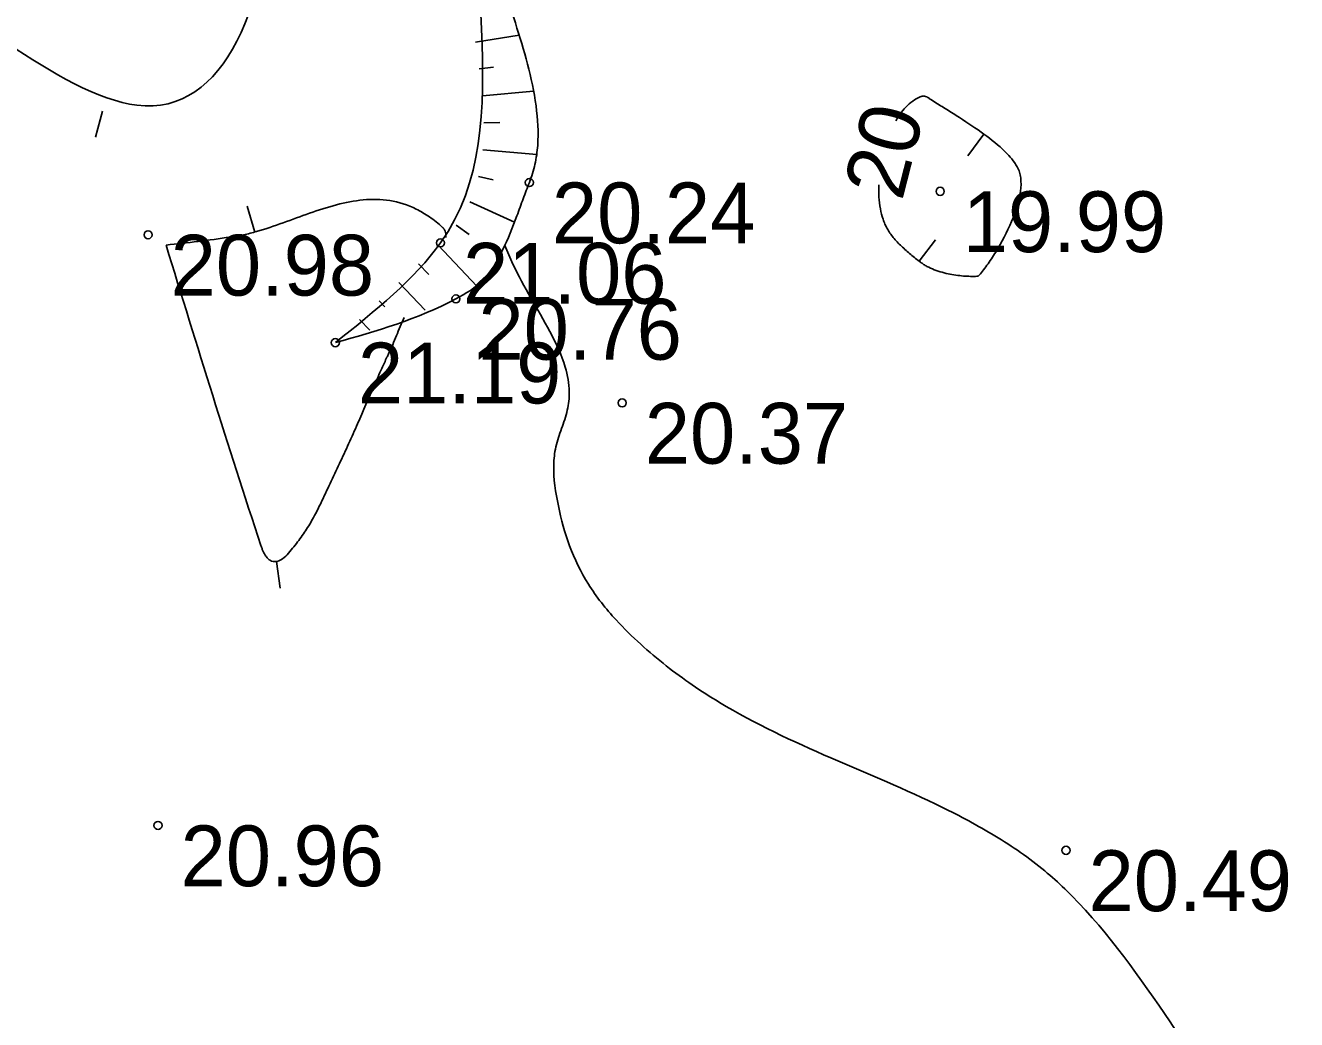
# Model space of a CAD drawing. Extents: x 521824 to 524158, y 294774 to 296228.
# Drawn here: x 522012.82 to 522036.35, y 295824.83 to 295843.22 of the extents above; entities that cross this region are included whole.
import ezdxf

# ---------------------------------------------------------------- set-up
doc = ezdxf.new("R2010")
doc.units = 0
for name, color, linetype in [('RELJ_AATZ_####_TKST_#', 7, 'Continuous'), ('RELJ_ELEM_####_####_#', 7, 'Continuous'), ('RELJ_HORZ_####_TKST_#', 7, 'Continuous'), ('RELJ_HORZ_PAMT_####_#', 7, 'Continuous'), ('RELJ_HORZ_RESN_####_#', 7, 'Continuous'), ('RELJ_NOGA_####_####_#', 7, 'Continuous'), ('RELJ_NOGL_####_####_#', 7, 'Continuous')]:
    doc.layers.add(name, color=color, linetype=linetype)

msp = doc.modelspace()

# ---------------------------------------------------------------- linework, layer by layer
at = {"layer": 'RELJ_ELEM_####_####_#'}
for centre in [(522022.146, 295840.316), (522029.749, 295840.153), (522015.09, 295839.349), (522020.50100000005, 295839.199), (522020.786, 295838.163), (522018.55600000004, 295837.353), (522023.864, 295836.238), (522015.27400000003, 295828.418), (522032.07800000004, 295827.957)]:
    msp.add_circle(centre, 0.075, dxfattribs=at)
at = {"layer": 'RELJ_HORZ_PAMT_####_#'}
for p, q in [((522014.11740016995, 295841.15612391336), (522014.2464446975, 295841.63918447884)), ((522016.92311437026, 295839.87930289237), (522017.0646110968, 295839.3997419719)), ((522017.53584021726, 295832.80696418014), (522017.4634709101, 295833.3016991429))]:
    msp.add_line(p, q, dxfattribs=at)
for points in [[(522039.85105248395, 295883.2337945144), (522039.8032764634, 295883.09412122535), (522039.6036826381, 295882.72640522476), (522038.55198012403, 295881.74642886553), (522037.24460411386, 295881.26963240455), (522035.87605298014, 295881.1684432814), (522029.62574498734, 295881.1250179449), (522028.3640343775, 295881.1156959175), (522027.73340432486, 295881.0942865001), (522027.10293182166, 295881.045318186), (522026.9348494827, 295880.8792425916), (522026.04491836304, 295879.0357926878), (522025.56662292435, 295877.8705193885), (522025.13096822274, 295876.6906595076), (522024.6784930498, 295875.509178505), (522024.1497361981, 295874.33904184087), (522023.1278022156, 295873.1202038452), (522022.45149386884, 295872.68855173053), (522021.718485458, 295872.3952945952), (522015.97858872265, 295871.9813647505), (522010.28566270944, 295873.3184813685), (522007.25729819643, 295874.6412358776), (522004.9722147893, 295876.36413812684), (522001.44201012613, 295878.6938834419), (521999.66114804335, 295879.6846711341), (521998.77242067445, 295880.0998103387), (521997.88697903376, 295880.44745277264), (521997.4959793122, 295880.4513396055), (521997.1092043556, 295880.23749301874), (521996.7340608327, 295879.87949182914), (521996.3779554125, 295879.45091485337), (521996.27616427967, 295879.0013078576), (521996.400274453, 295878.5538101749), (521996.8112803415, 295876.93516905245), (521997.1304580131, 295876.16157373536), (521997.6255973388, 295875.4531083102), (521999.24205179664, 295874.08337536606), (522001.01972147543, 295873.0615806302), (522002.8160713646, 295872.1323525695), (522003.67670919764, 295871.6226474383), (522004.48856645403, 295871.0403196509), (522005.06238406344, 295870.5370640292), (522005.6183839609, 295869.99889289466), (522006.1747109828, 295869.460970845), (522006.7495099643, 295868.9584624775), (522007.0070353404, 295868.85625760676), (522007.225831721, 295868.358889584), (522007.0915773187, 295860.8566492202), (522006.9208173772, 295855.8522134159), (522006.6846767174, 295848.9635027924), (522006.74219449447, 295846.87223905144), (522006.7634501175, 295846.5472356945), (522006.5524396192, 295845.2855568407), (522006.09686690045, 295844.1004188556), (522005.7434075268, 295843.61117697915), (522005.5208611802, 295843.426169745), (522005.262285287, 295843.2937742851), (522003.6445183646, 295843.19012527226), (522001.9994780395, 295843.7543531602), (522000.3301660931, 295844.5192909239), (521999.48734631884, 295844.83103631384), (521998.6395843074, 295845.01777153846), (521997.75563936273, 295845.08268233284), (521997.2109762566, 295844.8845836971), (521996.8583636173, 295844.45723979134), (521996.62520253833, 295844.00645984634), (521996.3326074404, 295843.04478261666), (521995.08116115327, 295838.05999353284), (521994.3171783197, 295833.02519397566), (521994.3254759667, 295831.74490356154), (521994.5353443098, 295830.4213550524), (521995.2569333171, 295829.63050990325), (521996.84168272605, 295828.8094427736), (521998.53761528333, 295828.25008483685), (522000.20764485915, 295827.67176067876), (522001.71468532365, 295826.7937948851), (522007.3320723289, 295820.83228229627), (522008.9147475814, 295818.1640307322), (522008.6042579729, 295814.9642406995), (522007.87451118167, 295814.0011593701), (522007.09756741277, 295813.11117719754), (522006.2702075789, 295812.2782132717), (522005.389212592, 295811.4861866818), (522001.2557309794, 295808.1438601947), (522000.1303116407, 295807.3706090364), (521998.96385563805, 295806.65336808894), (521997.7930222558, 295805.9482845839), (521996.6544707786, 295805.21150575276), (521996.38234203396, 295804.9480935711), (521996.15736309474, 295804.6301419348), (521995.9240970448, 295804.3146908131), (521995.6271069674, 295804.05878017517), (521994.03230866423, 295803.93852662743), (521993.54953046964, 295804.1273633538), (521993.0711955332, 295804.3438837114), (521992.5902990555, 295804.55881235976), (521992.0998362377, 295804.74287395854), (521988.9608554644, 295805.61124198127), (521982.64622882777, 295805.9659620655)], [(522008.128, 295848.335), (522008.2689477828, 295847.83384447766), (522012.49599618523, 295842.88903796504), (522014.8830624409, 295841.7470574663), (522016.1223240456, 295853.9072460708), (522015.27368849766, 295855.37330890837), (522014.846287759, 295856.25687423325), (522014.1497888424, 295858.06888958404), (522011.2980547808, 295858.5380575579), (522008.60002352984, 295854.29462215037), (522008.199583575, 295850.21910016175), (522008.128, 295848.335)], [(522020.59982497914, 295839.29797052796), (522020.60242294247, 295839.3453689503), (522020.59656443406, 295839.3927218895), (522020.5775423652, 295839.439193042), (522020.5616240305, 295839.46183660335), (522020.55180561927, 295839.47296464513), (522020.54639942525, 295839.4784745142), (522020.54064964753, 295839.4839461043), (522020.4189498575, 295839.58891256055), (522020.2970543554, 295839.68044139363), (522020.0527249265, 295839.82570962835), (522019.56225334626, 295839.98275244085), (522018.5767871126, 295839.9041759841), (522017.5904859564, 295839.571216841), (522017.0989707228, 295839.4102812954), (522016.85396291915, 295839.34886359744), (522016.6095848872, 295839.3068751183), (522015.422, 295839.158)], [(522015.422, 295839.158), (522017.17756001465, 295833.60029999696), (522017.19825370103, 295833.54041225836), (522017.22020120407, 295833.4876165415), (522017.2677147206, 295833.4026369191), (522017.31750571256, 295833.3474633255), (522017.34641107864, 295833.3261461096), (522017.37621522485, 295833.31047514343), (522017.51191183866, 295833.3153977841), (522017.6391055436, 295833.40014325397), (522017.7401793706, 295833.51719841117), (522017.8343231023, 295833.63474375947), (522018.00401694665, 295833.8732729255), (522018.1525804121, 295834.1196665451), (522018.2844068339, 295834.3778604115), (522018.45810594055, 295834.74571885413), (522018.6311366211, 295835.113454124), (522018.80147433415, 295835.48224132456), (522018.9670945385, 295835.8532555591), (522019.27671787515, 295836.5650211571), (522019.41559484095, 295836.8772227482), (522019.510905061, 295837.0835450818), (522019.5407993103, 295837.14613278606), (522019.6166244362, 295837.31422385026), (522019.6865798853, 295837.4830965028), (522019.75632240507, 295837.6510294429), (522019.8315087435, 295837.8163013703), (522019.83150875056, 295837.8163013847)], [(522061.741970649, 295824.8831938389), (522061.5520604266, 295824.78178038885), (522061.38605545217, 295824.74946375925), (522061.1718963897, 295824.81851527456), (522060.5310572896, 295824.96082909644), (522060.20688746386, 295824.9847778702), (522059.8960030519, 295824.9372926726), (522058.9889245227, 295824.33355464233), (522058.2956968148, 295823.37754064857), (522057.63291155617, 295822.3510845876), (522056.8171603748, 295821.5360203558), (522055.7262286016, 295820.8165031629), (522054.6152811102, 295820.105665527), (522053.4647294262, 295819.4691455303), (522052.25498507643, 295818.97258125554), (522047.30389492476, 295817.4178311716), (522043.97857530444, 295816.3212293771), (522043.21024391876, 295816.09499166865), (522042.41581105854, 295815.93624896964), (522041.62055172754, 295815.8963398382), (522041.2305105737, 295815.93699115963), (522040.8497409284, 295816.02660283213), (522039.80729485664, 295816.6465061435), (522038.94238886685, 295817.56506427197), (522037.1347181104, 295819.9756890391), (522035.5230144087, 295822.47335156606), (522033.8989985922, 295824.93675610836), (522032.05439149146, 295827.2446069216), (522031.68451634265, 295827.5776987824), (522030.7614068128, 295828.22486618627), (522029.7812756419, 295828.75707069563), (522027.7247754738, 295829.6683527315), (522025.66467003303, 295830.6950682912), (522024.680032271, 295831.37156470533), (522024.2072513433, 295831.7715715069), (522023.7506135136, 295832.2207407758), (522023.2382105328, 295832.8863053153), (522022.88963891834, 295833.5950921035), (522022.68313822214, 295834.33264938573), (522022.59694799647, 295835.08452540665), (522022.6368390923, 295835.42385731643), (522022.7423851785, 295835.763263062), (522022.8474568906, 295836.10303231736), (522022.88592486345, 295836.44345475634), (522022.81064079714, 295836.89677727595), (522022.5244666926, 295837.5583554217), (522022.1756120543, 295838.18152233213), (522021.8431745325, 295838.80350512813), (522021.6943038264, 295839.1549252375)], [(521998.95200000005, 295776.033), (521994.45180056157, 295777.14810434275), (521993.7404927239, 295777.11440045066), (521993.21262549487, 295776.6759437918), (521992.4953181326, 295775.0009956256), (521991.87608901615, 295772.9557067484), (521991.47081959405, 295772.05432420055), (521990.9311486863, 295771.37252406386), (521990.1398086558, 295770.77466894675), (521989.7352167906, 295770.4754847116), (521989.3530874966, 295770.1518434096), (521988.9164089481, 295769.6848393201), (521987.5681602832, 295767.21577675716), (521984.7771736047, 295762.2741632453), (521984.65230933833, 295760.3982510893), (521984.50330046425, 295759.4917473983), (521984.3585855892, 295758.58690105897), (521984.3353209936, 295757.6981352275), (521984.48002007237, 295757.3757561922), (521984.7063801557, 295757.0946927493), (521985.3082013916, 295756.7669212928), (521985.9519889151, 295756.72591082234), (521986.6068210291, 295756.80455120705), (521987.25649307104, 295756.9672667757), (521987.88480037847, 295757.17848185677), (521990.0305543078, 295757.99091302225), (521991.5170457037, 295758.46493880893), (521993.0217429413, 295758.88756110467), (521994.5233797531, 295759.3350657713), (521995.26640479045, 295759.59198832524), (521996.00068987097, 295759.88373867), (521997.05489538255, 295760.78736771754), (521997.55051264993, 295761.41710623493), (522000.3434912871, 295763.67917371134), (522000.94593386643, 295764.02787890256), (522003.2754265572, 295764.87055882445), (522004.55090309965, 295765.2234577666), (522005.83615178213, 295765.5370160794), (522007.12200246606, 295765.8503377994), (522008.3992850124, 295766.20252696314), (522009.65331824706, 295766.72165083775), (522011.3602020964, 295767.63989140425), (522012.969612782, 295768.6931675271), (522014.47229228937, 295769.89709722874), (522015.1807147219, 295770.5604378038), (522015.8589826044, 295771.26729853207), (522016.2597702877, 295771.87912286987), (522016.53298413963, 295772.5634778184), (522016.7931695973, 295773.25320618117), (522017.15487209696, 295773.88115076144), (522018.18949794, 295774.9696944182), (522018.4476509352, 295775.1878853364), (522019.2876896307, 295775.72172549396), (522020.4949333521, 295776.3014989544), (522021.6983824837, 295776.96563647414), (522022.26341950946, 295777.40953602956), (522022.5305948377, 295777.67347750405), (522022.78519040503, 295777.97075972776), (522023.2010017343, 295778.803778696), (522023.2392845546, 295779.6483704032), (522023.0122548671, 295780.4841053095), (522022.6658204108, 295781.3170062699), (522022.31136664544, 295782.1521974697), (522022.0602790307, 295782.9948030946), (522021.8800262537, 295784.34168614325), (522021.8683239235, 295785.71352772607), (522021.9466292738, 295786.68962457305), (522022.13179647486, 295787.705289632), (522022.5219133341, 295788.5528666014), (522023.2150676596, 295789.0246991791), (522026.40113487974, 295789.6656407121), (522029.5910643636, 295790.20565416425), (522031.1198177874, 295790.45930455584), (522031.8833809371, 295790.592832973), (522032.2641433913, 295790.66813436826), (522032.6439156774, 295790.75174108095), (522034.34009166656, 295791.613047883), (522035.89075127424, 295792.7974618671), (522039.32693267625, 295795.1720253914), (522041.99268416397, 295796.8267501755), (522044.5121990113, 295798.984097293), (522044.9056368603, 295799.5506320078), (522045.47650309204, 295800.55810906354), (522045.99759169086, 295801.59089799), (522046.5214402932, 295802.62769177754), (522047.1005865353, 295803.6471834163), (522049.4664640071, 295806.9793396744), (522050.94743011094, 295808.28937408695), (522051.7905227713, 295808.76012787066), (522052.71272765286, 295809.0717527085), (522053.5514493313, 295809.2031588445), (522054.3939016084, 295809.26977886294), (522056.18416763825, 295809.39970149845), (522057.9448874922, 295809.5837619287), (522059.7026316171, 295809.81589361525), (522061.4611590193, 295810.04426197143), (522063.22422870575, 295810.21703241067), (522064.1655150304, 295810.1470657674), (522066.93228605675, 295809.9065813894), (522068.31554527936, 295810.0098516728), (522069.00682868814, 295810.20883838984), (522069.35234451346, 295810.3566038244), (522069.69776143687, 295810.5409065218), (522070.4955259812, 295811.1688285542), (522071.0813307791, 295811.9043088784), (522071.5717992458, 295812.6925002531), (522071.81772717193, 295813.0892228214), (522072.08355479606, 295813.4785554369), (522072.40604720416, 295814.0003097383), (522072.7676993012, 295814.4937868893), (522073.1254027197, 295814.75396744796), (522073.5336405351, 295814.93279178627), (522073.95939591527, 295815.08768923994), (522074.369652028, 295815.27608914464), (522075.0954593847, 295815.66872097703), (522075.81475551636, 295816.0696827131), (522076.4764910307, 295816.5373865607), (522076.76982062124, 295816.81452059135), (522077.029616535, 295817.1302447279), (522077.3485357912, 295818.0711955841), (522077.2140011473, 295819.12112619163), (522076.82493924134, 295820.19231449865), (522076.38027671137, 295821.19703845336), (522075.40752943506, 295823.31140125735), (522075.07482163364, 295824.3220648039), (522074.8158376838, 295825.3634059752), (522074.5088306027, 295826.3931939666), (522074.2992724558, 295826.89055839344), (522074.0320534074, 295827.3691979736), (522073.5498181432, 295827.83794916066), (522072.9888231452, 295828.2044779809), (522072.5737168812, 295828.40410874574), (522072.0614797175, 295828.59496277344), (522071.7062148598, 295828.76573362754), (522071.6668542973, 295828.8400546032), (522071.7620255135, 295828.9051148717), (522072.44228643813, 295829.09140054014), (522073.12896814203, 295829.19107671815), (522075.3108758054, 295828.6989870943), (522076.9489012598, 295827.7002041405), (522079.1396826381, 295828.4298136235), (522079.996228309, 295829.49230765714), (522079.62960017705, 295830.75335929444), (522079.41251941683, 295831.52017392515)]]:
    msp.add_spline(points, degree=3, dxfattribs=at)
at = {"layer": 'RELJ_HORZ_RESN_####_#'}
for p, q in [((522030.2618123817, 295840.80913771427), (522030.55606014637, 295841.21338794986)), ((522029.6653020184, 295839.25665146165), (522029.3593626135, 295838.8611756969))]:
    msp.add_line(p, q, dxfattribs=at)
for points in [[(522030.4550113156, 295838.58175111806), (522030.5329291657, 295838.6768835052), (522030.61357157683, 295838.78453507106), (522030.77694118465, 295839.0302383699), (522031.0693972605, 295839.59314406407), (522031.234957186, 295840.1559503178), (522031.23970660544, 295840.40152931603), (522031.2172458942, 295840.50910008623), (522031.1991407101, 295840.558297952), (522031.1882861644, 295840.58165215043), (522031.17619860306, 295840.60413924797), (522031.1228061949, 295840.68678699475), (522030.90318291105, 295840.9313983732), (522030.5068557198, 295841.2488145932), (522030.0475793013, 295841.55474572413), (522029.8131983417, 295841.7028911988), (522029.5857159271, 295841.8475495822), (522029.5437247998, 295841.87505110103), (522029.4996840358, 295841.90052567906), (522029.4560327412, 295841.91610713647), (522029.43511536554, 295841.9177297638), (522029.4250171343, 295841.9165688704), (522029.41521002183, 295841.9139292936), (522029.2741144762, 295841.84425091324), (522029.1452147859, 295841.74226743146), (522029.0290034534, 295841.6122194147), (522028.9758098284, 295841.5379963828), (522028.9259729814, 295841.45834742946)], [(522028.61227817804, 295840.2763621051), (522028.6117358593, 295840.16062782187), (522028.6166437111, 295840.047533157), (522028.64317076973, 295839.8323696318), (522028.6925810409, 295839.6370854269), (522028.7260929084, 295839.54883991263), (522028.74508999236, 295839.50740612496), (522028.76559621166, 295839.46789443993), (522028.8817430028, 295839.2996473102), (522029.03233743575, 295839.1383042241), (522029.20417272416, 295838.98532258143), (522029.2939285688, 295838.91242273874), (522029.38404208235, 295838.84215978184), (522029.4425571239, 295838.8011400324), (522029.5052402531, 295838.7642572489), (522029.6405004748, 295838.70218451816), (522029.93232467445, 295838.6197839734), (522030.21774988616, 295838.5834691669), (522030.34501137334, 295838.5790036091), (522030.40249532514, 295838.57956548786), (522030.4550113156, 295838.58175111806)]]:
    msp.add_spline(points, degree=3, dxfattribs=at)
at = {"layer": 'RELJ_NOGA_####_####_#'}
for p, q in [((522021.1463987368, 295842.91255650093), (522021.95668490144, 295843.04196290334)), ((522021.2201645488, 295842.41804363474), (522021.4846160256, 295842.4533990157)), ((522021.2761571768, 295841.92123562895), (522022.2241062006, 295842.00710660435)), ((522021.3028946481, 295841.42206164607), (522021.6019640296, 295841.42745515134)), ((522021.2852698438, 295840.92260808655), (522022.28235274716, 295840.8354025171)), ((522021.2049488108, 295840.42956618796), (522021.4747006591, 295840.3634775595)), ((522021.0434406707, 295839.95716491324), (522021.87192941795, 295839.581280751)), ((522020.79116274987, 295839.52655083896), (522021.03025439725, 295839.35172327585)), ((522020.4561429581, 295839.15642617), (522021.17531129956, 295838.3986892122)), ((522020.0934803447, 295838.81222299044), (522020.2842050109, 295838.61126986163)), ((522019.7308177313, 295838.46801981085), (522020.2166054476, 295837.9561795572)), ((522019.3681551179, 295838.1238166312), (522019.46890308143, 295838.0176656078)), ((522019.0054925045, 295837.77961345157), (522019.19135787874, 295837.58378021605)), ((522018.6428298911, 295837.435410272), (522018.65360115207, 295837.424061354))]:
    msp.add_line(p, q, dxfattribs=at)
msp.add_spline([(522018.55600000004, 295837.353), (522020.50100000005, 295839.199), (522021.477, 295848.18), (522028.416, 295855.248), (522030.764, 295852.519), (522039.31600000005, 295853.821), (522047.42000000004, 295849.505), (522051.81100000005, 295848.394), (522054.114, 295850.7040000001), (522056.37600000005, 295853.1390000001), (522063.96900000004, 295845.04000000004)], degree=3, dxfattribs=at)
at = {"layer": 'RELJ_NOGL_####_####_#'}
msp.add_spline([(522018.55600000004, 295837.353), (522020.786, 295838.163), (522021.29201399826, 295838.51486265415), (522021.65031370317, 295839.06336455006), (522021.9164565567, 295839.69993417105), (522022.0323308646, 295840.01731577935), (522022.146, 295840.316), (522022.2497575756, 295840.65282321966), (522022.3000511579, 295841.0028959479), (522022.26939318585, 295841.73475341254), (522021.8871245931, 295843.26906074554), (522021.4655437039, 295844.7903377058), (522021.38574536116, 295845.50590720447), (522021.471, 295846.17000000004), (522021.55386910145, 295846.3219582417), (522021.6882953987, 295846.41378726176), (522022.0827355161, 295846.4508374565), (522023.1703773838, 295846.17496520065), (522024.26858055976, 295845.88286034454), (522024.676222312, 295845.89961978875), (522024.81922967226, 295845.9782598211), (522024.912, 295846.115), (522024.8306145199, 295846.7553688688), (522024.3916502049, 295847.48063000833), (522023.97001916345, 295848.2214333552), (522023.9406335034, 295848.90842884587)], degree=3, dxfattribs=at)

# ---------------------------------------------------------------- texts
at = {"layer": 'RELJ_AATZ_####_TKST_#'}
for s, p in [(' 20.24', (522022.146, 295839.191)), (' 19.99', (522029.749, 295839.028)), (' 20.98', (522015.09, 295838.224)), (' 21.06', (522020.50100000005, 295838.074)), (' 20.76', (522020.786, 295837.038)), (' 21.19', (522018.55600000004, 295836.228)), (' 20.37', (522023.864, 295835.113)), (' 20.96', (522015.27400000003, 295827.293)), (' 20.49', (522032.07800000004, 295826.832))]:
    msp.add_text(s, height=1.125, dxfattribs=at).set_placement(p)
at = {"layer": 'RELJ_HORZ_####_TKST_#'}
msp.add_text('20', height=1.1249999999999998, rotation=75.66136157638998, dxfattribs=at).set_placement((522029.04171979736, 295839.95831966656))

doc.saveas('drawing.dxf')
